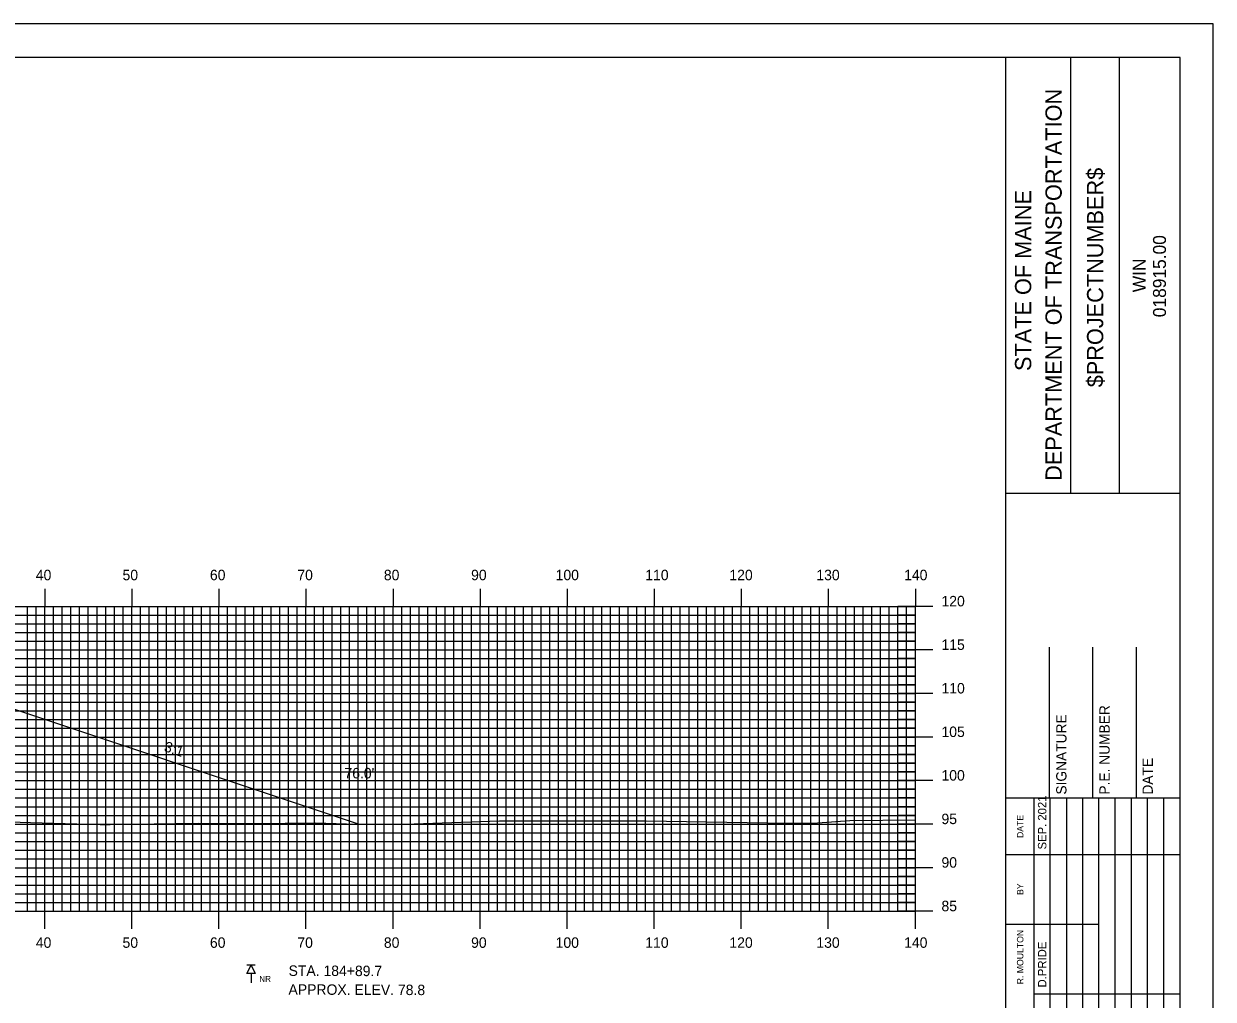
# Model space of a CAD drawing. Extents: x 1786976 to 1787319, y 442591 to 442811.
# Drawn here: x 1787179.2 to 1787315.8, y 442698.6 to 442810.5 of the extents above; entities that cross this region are included whole.
import ezdxf

# ---------------------------------------------------------------- set-up
doc = ezdxf.new("R2010")
doc.units = 0
for name, color, linetype in [('ANNOTATION', 7, 'Continuous'), ('BORDER', 7, 'Continuous'), ('BORING - NO REFUSAL', 7, 'Continuous'), ('D_Roadway_Centerline', 7, 'Continuous'), ('D_Roadway_SlopeLines', 7, 'Continuous'), ('D_Text_Standard', 7, 'Continuous'), ('H_V ANNOTATION', 7, 'Continuous'), ('MAJOR', 7, 'Continuous'), ('MINOR', 7, 'Continuous'), ('PLOT BOUNDARY', 7, 'Continuous'), ('S_Roadway_Centerline', 7, 'Continuous')]:
    doc.layers.add(name, color=color, linetype=linetype)

msp = doc.modelspace()

# ---------------------------------------------------------------- linework, layer by layer
at = {"layer": 'BORDER'}
for p, q in [((1787291.99, 442596.67), (1787291.99, 442806.67)), ((1787299.45, 442756.66), (1787299.45, 442806.66)), ((1787305.04, 442756.66), (1787305.04, 442806.66)), ((1787291.99, 442756.65), (1787311.99, 442756.65)), ((1787296.99, 442721.67), (1787296.99, 442738.97)), ((1787301.99, 442721.67), (1787301.99, 442738.97)), ((1787306.99, 442721.67), (1787306.99, 442738.97)), ((1787291.99, 442721.67), (1787311.99, 442721.67))]:
    msp.add_line(p, q, dxfattribs=at)
msp.add_lwpolyline([(1786991.99, 442596.67), (1787311.99, 442596.67), (1787311.99, 442806.67), (1786991.99, 442806.67)], close=True, dxfattribs=at)
for points in [[(1787295.22, 442715.17), (1787295.22, 442721.67)], [(1787297.09, 442686.68), (1787297.09, 442721.67)], [(1787298.95, 442721.67), (1787298.95, 442686.68)], [(1787300.81, 442686.68), (1787300.81, 442721.67)], [(1787302.68, 442686.68), (1787302.68, 442721.67)], [(1787304.54, 442686.68), (1787304.54, 442721.67)], [(1787306.4, 442686.68), (1787306.4, 442721.67)], [(1787308.27, 442686.68), (1787308.27, 442721.67)], [(1787310.13, 442686.68), (1787310.13, 442721.67)], [(1787295.22, 442686.68), (1787295.22, 442720.26)], [(1787291.99, 442715.17), (1787311.99, 442715.17)], [(1787291.99, 442707.17), (1787295.22, 442707.17)], [(1787295.22, 442707.17), (1787302.67, 442707.17)], [(1787295.22, 442699.17), (1787311.99, 442699.17)]]:
    msp.add_lwpolyline(points, dxfattribs=at)
at = {"layer": 'BORING - NO REFUSAL'}
for p, q in [((1787205.77, 442702.47), (1787204.81, 442702.47)), ((1787205.29, 442701.51), (1787205.29, 442700.45))]:
    msp.add_line(p, q, dxfattribs=at)
msp.add_lwpolyline([(1787205.29, 442702.47), (1787205.77, 442701.51), (1787204.81, 442701.51)], close=True, dxfattribs=at)
at = {"layer": 'D_Roadway_Centerline'}
msp.add_lwpolyline([(1787067.21, 442719.86), (1787105.66, 442732.68), (1787109.64, 442733.68), (1787117.66, 442735.68), (1787129.59, 442736.16), (1787141.59, 442736.42), (1787153.59, 442736.69), (1787161.59, 442736.37), (1787169.95, 442734.28), (1787173.59, 442733.37), (1787217.6, 442718.7)], dxfattribs=at)
at = {"layer": 'D_Roadway_SlopeLines'}
msp.add_lwpolyline([(1787161.59, 442736.37), (1787173.59, 442733.37), (1787217.6, 442718.7)], dxfattribs=at)
at = {"layer": 'MAJOR'}
for p, q in [((1787181.59, 442745.67), (1787181.59, 442743.67)), ((1787191.59, 442745.67), (1787191.59, 442743.67)), ((1787201.59, 442745.67), (1787201.59, 442743.67)), ((1787211.59, 442745.67), (1787211.59, 442743.67)), ((1787221.59, 442745.67), (1787221.59, 442743.67)), ((1787231.59, 442745.67), (1787231.59, 442743.67)), ((1787241.59, 442745.67), (1787241.59, 442743.67)), ((1787251.59, 442745.67), (1787251.59, 442743.67)), ((1787261.59, 442745.67), (1787261.59, 442743.67)), ((1787271.59, 442745.67), (1787271.59, 442743.67)), ((1787281.59, 442745.67), (1787281.59, 442743.67)), ((1787001.59, 442743.67), (1787281.59, 442743.67)), ((1787001.59, 442743.67), (1787281.59, 442743.67)), ((1787181.59, 442708.67), (1787181.59, 442743.67)), ((1787191.59, 442708.67), (1787191.59, 442743.67)), ((1787201.59, 442708.67), (1787201.59, 442743.67)), ((1787211.59, 442708.67), (1787211.59, 442743.67)), ((1787221.59, 442708.67), (1787221.59, 442743.67)), ((1787231.59, 442708.67), (1787231.59, 442743.67)), ((1787241.59, 442708.67), (1787241.59, 442743.67)), ((1787251.59, 442708.67), (1787251.59, 442743.67)), ((1787261.59, 442708.67), (1787261.59, 442743.67)), ((1787271.59, 442708.67), (1787271.59, 442743.67)), ((1787283.6, 442743.67), (1787279.59, 442743.67)), ((1787281.59, 442708.67), (1787281.59, 442743.67)), ((1787281.59, 442708.67), (1787281.59, 442743.67)), ((1787001.59, 442738.67), (1787281.59, 442738.67)), ((1787283.6, 442738.67), (1787279.59, 442738.67)), ((1787001.59, 442733.67), (1787281.59, 442733.67)), ((1787283.6, 442733.67), (1787279.59, 442733.67)), ((1787001.59, 442728.67), (1787281.59, 442728.67)), ((1787283.6, 442728.67), (1787279.59, 442728.67)), ((1787001.59, 442723.67), (1787281.59, 442723.67)), ((1787283.6, 442723.67), (1787279.59, 442723.67)), ((1787001.59, 442718.67), (1787281.59, 442718.67)), ((1787283.6, 442718.67), (1787279.59, 442718.67)), ((1787001.59, 442713.67), (1787281.59, 442713.67)), ((1787283.6, 442713.67), (1787279.59, 442713.67)), ((1787001.59, 442708.67), (1787281.59, 442708.67)), ((1787001.59, 442708.67), (1787281.59, 442708.67)), ((1787181.59, 442706.66), (1787181.59, 442708.67)), ((1787191.59, 442706.66), (1787191.59, 442708.67)), ((1787201.59, 442706.66), (1787201.59, 442708.67)), ((1787211.59, 442706.66), (1787211.59, 442708.67)), ((1787221.59, 442706.66), (1787221.59, 442708.67)), ((1787231.59, 442706.66), (1787231.59, 442708.67)), ((1787241.59, 442706.66), (1787241.59, 442708.67)), ((1787251.59, 442706.66), (1787251.59, 442708.67)), ((1787261.59, 442706.66), (1787261.59, 442708.67)), ((1787271.59, 442706.66), (1787271.59, 442708.67)), ((1787283.6, 442708.67), (1787279.59, 442708.67)), ((1787281.59, 442706.66), (1787281.59, 442708.67))]:
    msp.add_line(p, q, dxfattribs=at)
at = {"layer": 'MINOR'}
for p, q in [((1787179.59, 442708.67), (1787179.59, 442743.67)), ((1787180.59, 442708.67), (1787180.59, 442743.67)), ((1787182.59, 442708.67), (1787182.59, 442743.67)), ((1787183.59, 442708.67), (1787183.59, 442743.67)), ((1787184.59, 442708.67), (1787184.59, 442743.67)), ((1787185.59, 442708.67), (1787185.59, 442743.67)), ((1787186.59, 442708.67), (1787186.59, 442743.67)), ((1787187.59, 442708.67), (1787187.59, 442743.67)), ((1787188.59, 442708.67), (1787188.59, 442743.67)), ((1787189.59, 442708.67), (1787189.59, 442743.67)), ((1787190.59, 442708.67), (1787190.59, 442743.67)), ((1787192.59, 442708.67), (1787192.59, 442743.67)), ((1787193.59, 442708.67), (1787193.59, 442743.67)), ((1787194.59, 442708.67), (1787194.59, 442743.67)), ((1787195.59, 442708.67), (1787195.59, 442743.67)), ((1787196.59, 442708.67), (1787196.59, 442743.67)), ((1787197.59, 442708.67), (1787197.59, 442743.67)), ((1787198.59, 442708.67), (1787198.59, 442743.67)), ((1787199.59, 442708.67), (1787199.59, 442743.67)), ((1787200.59, 442708.67), (1787200.59, 442743.67)), ((1787202.59, 442708.67), (1787202.59, 442743.67)), ((1787203.59, 442708.67), (1787203.59, 442743.67)), ((1787204.59, 442708.67), (1787204.59, 442743.67)), ((1787205.59, 442708.67), (1787205.59, 442743.67)), ((1787206.59, 442708.67), (1787206.59, 442743.67)), ((1787207.59, 442708.67), (1787207.59, 442743.67)), ((1787208.59, 442708.67), (1787208.59, 442743.67)), ((1787209.59, 442708.67), (1787209.59, 442743.67)), ((1787210.59, 442708.67), (1787210.59, 442743.67)), ((1787212.59, 442708.67), (1787212.59, 442743.67)), ((1787213.59, 442708.67), (1787213.59, 442743.67)), ((1787214.59, 442708.67), (1787214.59, 442743.67)), ((1787215.59, 442708.67), (1787215.59, 442743.67)), ((1787216.59, 442708.67), (1787216.59, 442743.67)), ((1787217.59, 442708.67), (1787217.59, 442743.67)), ((1787218.59, 442708.67), (1787218.59, 442743.67)), ((1787219.59, 442708.67), (1787219.59, 442743.67)), ((1787220.59, 442708.67), (1787220.59, 442743.67)), ((1787222.59, 442708.67), (1787222.59, 442743.67)), ((1787223.59, 442708.67), (1787223.59, 442743.67)), ((1787224.59, 442708.67), (1787224.59, 442743.67)), ((1787225.59, 442708.67), (1787225.59, 442743.67)), ((1787226.59, 442708.67), (1787226.59, 442743.67)), ((1787227.59, 442708.67), (1787227.59, 442743.67)), ((1787228.59, 442708.67), (1787228.59, 442743.67)), ((1787229.59, 442708.67), (1787229.59, 442743.67)), ((1787230.59, 442708.67), (1787230.59, 442743.67)), ((1787232.59, 442708.67), (1787232.59, 442743.67)), ((1787233.59, 442708.67), (1787233.59, 442743.67)), ((1787234.59, 442708.67), (1787234.59, 442743.67)), ((1787235.59, 442708.67), (1787235.59, 442743.67)), ((1787236.59, 442708.67), (1787236.59, 442743.67)), ((1787237.59, 442708.67), (1787237.59, 442743.67)), ((1787238.59, 442708.67), (1787238.59, 442743.67)), ((1787239.59, 442708.67), (1787239.59, 442743.67)), ((1787240.59, 442708.67), (1787240.59, 442743.67)), ((1787242.59, 442708.67), (1787242.59, 442743.67)), ((1787243.59, 442708.67), (1787243.59, 442743.67)), ((1787244.59, 442708.67), (1787244.59, 442743.67)), ((1787245.59, 442708.67), (1787245.59, 442743.67)), ((1787246.59, 442708.67), (1787246.59, 442743.67)), ((1787247.59, 442708.67), (1787247.59, 442743.67)), ((1787248.59, 442708.67), (1787248.59, 442743.67)), ((1787249.59, 442708.67), (1787249.59, 442743.67)), ((1787250.59, 442708.67), (1787250.59, 442743.67)), ((1787252.59, 442708.67), (1787252.59, 442743.67)), ((1787253.59, 442708.67), (1787253.59, 442743.67)), ((1787254.59, 442708.67), (1787254.59, 442743.67)), ((1787255.59, 442708.67), (1787255.59, 442743.67)), ((1787256.59, 442708.67), (1787256.59, 442743.67)), ((1787257.59, 442708.67), (1787257.59, 442743.67)), ((1787258.59, 442708.67), (1787258.59, 442743.67)), ((1787259.59, 442708.67), (1787259.59, 442743.67)), ((1787260.59, 442708.67), (1787260.59, 442743.67)), ((1787262.59, 442708.67), (1787262.59, 442743.67)), ((1787263.59, 442708.67), (1787263.59, 442743.67)), ((1787264.59, 442708.67), (1787264.59, 442743.67)), ((1787265.59, 442708.67), (1787265.59, 442743.67)), ((1787266.59, 442708.67), (1787266.59, 442743.67)), ((1787267.59, 442708.67), (1787267.59, 442743.67)), ((1787268.59, 442708.67), (1787268.59, 442743.67)), ((1787269.59, 442708.67), (1787269.59, 442743.67)), ((1787270.59, 442708.67), (1787270.59, 442743.67)), ((1787272.59, 442708.67), (1787272.59, 442743.67)), ((1787273.59, 442708.67), (1787273.59, 442743.67)), ((1787274.59, 442708.67), (1787274.59, 442743.67)), ((1787275.59, 442708.67), (1787275.59, 442743.67)), ((1787276.59, 442708.67), (1787276.59, 442743.67)), ((1787277.59, 442708.67), (1787277.59, 442743.67)), ((1787278.59, 442708.67), (1787278.59, 442743.67)), ((1787279.59, 442708.67), (1787279.59, 442743.67)), ((1787280.59, 442708.67), (1787280.59, 442743.67)), ((1787001.59, 442742.67), (1787281.59, 442742.67)), ((1787001.59, 442741.67), (1787281.59, 442741.67)), ((1787281.59, 442742.67), (1787279.59, 442742.67)), ((1787281.59, 442741.67), (1787279.59, 442741.67)), ((1787001.59, 442740.67), (1787281.59, 442740.67)), ((1787281.59, 442740.67), (1787279.59, 442740.67)), ((1787001.59, 442739.67), (1787281.59, 442739.67)), ((1787281.59, 442739.67), (1787279.59, 442739.67)), ((1787001.59, 442737.67), (1787281.59, 442737.67)), ((1787281.59, 442737.67), (1787279.59, 442737.67)), ((1787001.59, 442736.67), (1787281.59, 442736.67)), ((1787281.59, 442736.67), (1787279.59, 442736.67)), ((1787001.59, 442735.67), (1787281.59, 442735.67)), ((1787281.59, 442735.67), (1787279.59, 442735.67)), ((1787001.59, 442734.67), (1787281.59, 442734.67)), ((1787281.59, 442734.67), (1787279.59, 442734.67)), ((1787001.59, 442732.67), (1787281.59, 442732.67)), ((1787281.59, 442732.67), (1787279.59, 442732.67)), ((1787001.59, 442731.67), (1787281.59, 442731.67)), ((1787001.59, 442730.67), (1787281.59, 442730.67)), ((1787281.59, 442731.67), (1787279.59, 442731.67)), ((1787281.59, 442730.67), (1787279.59, 442730.67)), ((1787001.59, 442729.67), (1787281.59, 442729.67)), ((1787281.59, 442729.67), (1787279.59, 442729.67)), ((1787001.59, 442727.67), (1787281.59, 442727.67)), ((1787001.59, 442726.67), (1787281.59, 442726.67)), ((1787281.59, 442727.67), (1787279.59, 442727.67)), ((1787281.59, 442726.67), (1787279.59, 442726.67)), ((1787001.59, 442725.67), (1787281.59, 442725.67)), ((1787281.59, 442725.67), (1787279.59, 442725.67)), ((1787001.59, 442724.67), (1787281.59, 442724.67)), ((1787281.59, 442724.67), (1787279.59, 442724.67)), ((1787001.59, 442722.67), (1787281.59, 442722.67)), ((1787281.59, 442722.67), (1787279.59, 442722.67)), ((1787001.59, 442721.67), (1787281.59, 442721.67)), ((1787281.59, 442721.67), (1787279.59, 442721.67)), ((1787001.59, 442720.67), (1787281.59, 442720.67)), ((1787281.59, 442720.67), (1787279.59, 442720.67)), ((1787001.59, 442719.67), (1787281.59, 442719.67)), ((1787281.59, 442719.67), (1787279.59, 442719.67)), ((1787001.59, 442717.67), (1787281.59, 442717.67)), ((1787281.59, 442717.67), (1787279.59, 442717.67)), ((1787001.59, 442716.67), (1787281.59, 442716.67)), ((1787001.59, 442715.67), (1787281.59, 442715.67)), ((1787281.59, 442716.67), (1787279.59, 442716.67)), ((1787281.59, 442715.67), (1787279.59, 442715.67)), ((1787001.59, 442714.67), (1787281.59, 442714.67)), ((1787281.59, 442714.67), (1787279.59, 442714.67)), ((1787001.59, 442712.67), (1787281.59, 442712.67)), ((1787001.59, 442711.67), (1787281.59, 442711.67)), ((1787281.59, 442712.67), (1787279.59, 442712.67)), ((1787281.59, 442711.67), (1787279.59, 442711.67)), ((1787001.59, 442710.67), (1787281.59, 442710.67)), ((1787281.59, 442710.67), (1787279.59, 442710.67)), ((1787001.59, 442709.67), (1787281.59, 442709.67)), ((1787281.59, 442709.67), (1787279.59, 442709.67))]:
    msp.add_line(p, q, dxfattribs=at)
at = {"layer": 'PLOT BOUNDARY'}
msp.add_lwpolyline([(1786975.8, 442590.55), (1787315.8, 442590.55), (1787315.8, 442810.55), (1786975.8, 442810.55)], close=True, dxfattribs=at)
at = {"layer": 'S_Roadway_Centerline'}
msp.add_lwpolyline([(1787171.7, 442719.13), (1787179.96, 442718.85), (1787187.95, 442718.61), (1787188.25, 442718.61), (1787188.56, 442718.61), (1787189.1, 442718.61), (1787199.19, 442718.78), (1787205.69, 442718.74), (1787212.69, 442718.81), (1787216.26, 442718.7), (1787222.95, 442718.67), (1787227.25, 442718.81), (1787233.81, 442719.03), (1787245.48, 442719.06), (1787246.46, 442719.04), (1787247.13, 442719.05), (1787250.68, 442719.03), (1787266.92, 442718.77), (1787270.35, 442718.8), (1787274.07, 442719.1), (1787281.59, 442719.18)], dxfattribs=at)

# ---------------------------------------------------------------- texts
at = {"layer": 'ANNOTATION'}
msp.add_text('3:1', height=1.2, rotation=341.5652, dxfattribs=at).set_placement((1787195.2, 442727.07))
at = {"layer": 'BORDER'}
for s, height, p in [('DEPARTMENT OF TRANSPORTATION', 1.8635, (1787298.4, 442758.08)), ('$PROJECTNUMBER$', 1.8635, (1787303.17, 442768.82)), ('STATE OF MAINE', 1.8635, (1787294.9, 442770.69)), ('018915.00', 1.491, (1787310.38, 442776.86)), ('WIN', 1.491, (1787308.06, 442779.73)), ('P.E. NUMBER', 1.1811, (1787303.91, 442722.06)), ('SIGNATURE', 1.181, (1787298.95, 442722.06)), ('DATE', 1.181, (1787308.87, 442722.06)), ('SEP. 2021', 0.969, (1787296.64, 442715.76)), ('DATE', 0.743, (1787294, 442717.08)), ('BY', 0.743, (1787294, 442710.54)), ('R. MOULTON', 0.745, (1787294, 442700.28)), ('D.PRIDE', 0.969, (1787296.64, 442699.92))]:
    msp.add_text(s, height=height, rotation=90, dxfattribs=at).set_placement(p)
at = {"layer": 'BORING - NO REFUSAL'}
for s, p in [('STA. 184+89.7', (1787209.59, 442701.25)), ('APPROX. ELEV. 78.8', (1787209.58, 442699.09))]:
    msp.add_text(s, height=1.2, rotation=359.8142, dxfattribs=at).set_placement(p)
msp.add_text('NR', height=0.7, dxfattribs=at).set_placement((1787206.22, 442700.55))
at = {"layer": 'D_Text_Standard'}
msp.add_text("76.0'", height=1.2, dxfattribs=at).set_placement((1787216.01, 442723.92))
at = {"layer": 'H_V ANNOTATION'}
for s, p in [('40', (1787180.56, 442746.67)), ('50', (1787190.52, 442746.67)), ('60', (1787200.56, 442746.67)), ('70', (1787210.6, 442746.67)), ('80', (1787220.54, 442746.67)), ('90', (1787230.56, 442746.67)), ('100', (1787240.27, 442746.67)), ('110', (1787250.57, 442746.67)), ('120', (1787260.23, 442746.67)), ('130', (1787270.22, 442746.67)), ('140', (1787280.3, 442746.67)), ('120', (1787284.59, 442743.67)), ('115', (1787284.59, 442738.67)), ('110', (1787284.59, 442733.67)), ('105', (1787284.59, 442728.67)), ('100', (1787284.59, 442723.67)), ('95', (1787284.59, 442718.67)), ('90', (1787284.59, 442713.67)), ('85', (1787284.59, 442708.67)), ('40', (1787180.56, 442704.47)), ('50', (1787190.52, 442704.47)), ('60', (1787200.56, 442704.47)), ('70', (1787210.6, 442704.47)), ('80', (1787220.54, 442704.47)), ('90', (1787230.56, 442704.47)), ('100', (1787240.27, 442704.47)), ('110', (1787250.57, 442704.47)), ('120', (1787260.23, 442704.47)), ('130', (1787270.22, 442704.47)), ('140', (1787280.3, 442704.47))]:
    msp.add_text(s, height=1.2, dxfattribs=at).set_placement(p)

doc.saveas('drawing.dxf')
